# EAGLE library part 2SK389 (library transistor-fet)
DUAL FIELD EFFECT TRANSISTOR SILICON MONOLITHIC N CHANNEL JUNCTION TYPE Source: http://pdf1.alldatasheet.com/datasheet-pdf/view/30769/TOSHIBA/2SK389.html
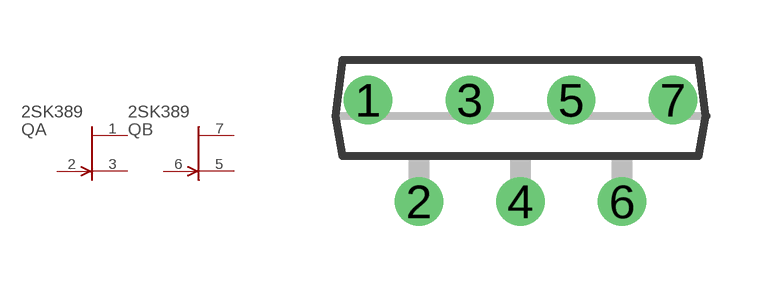
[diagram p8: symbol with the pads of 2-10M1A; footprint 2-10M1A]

Designator prefix Q; gates A=JFET_N B=JFET_N

## 2SK389  [2-10M1A]
1  A:D  pas
2  A:G  pas
3  A:S  pas
5  B:S  pas
6  B:G  pas
7  B:D  pas

## Footprint 2-10M1A (pad centres in mm)
Single In Line 2-10M1A Source: http://pdf1.alldatasheet.com/datasheet-pdf/view/30769/TOSHIBA/2SK389.html
drill 0.7 pad 1.2 round: 1 -3.81,0; 2 -2.54,-2.54; 3 -1.27,0; 4 0,-2.54; 5 1.27,0; 6 2.54,-2.54; 7 3.81,0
